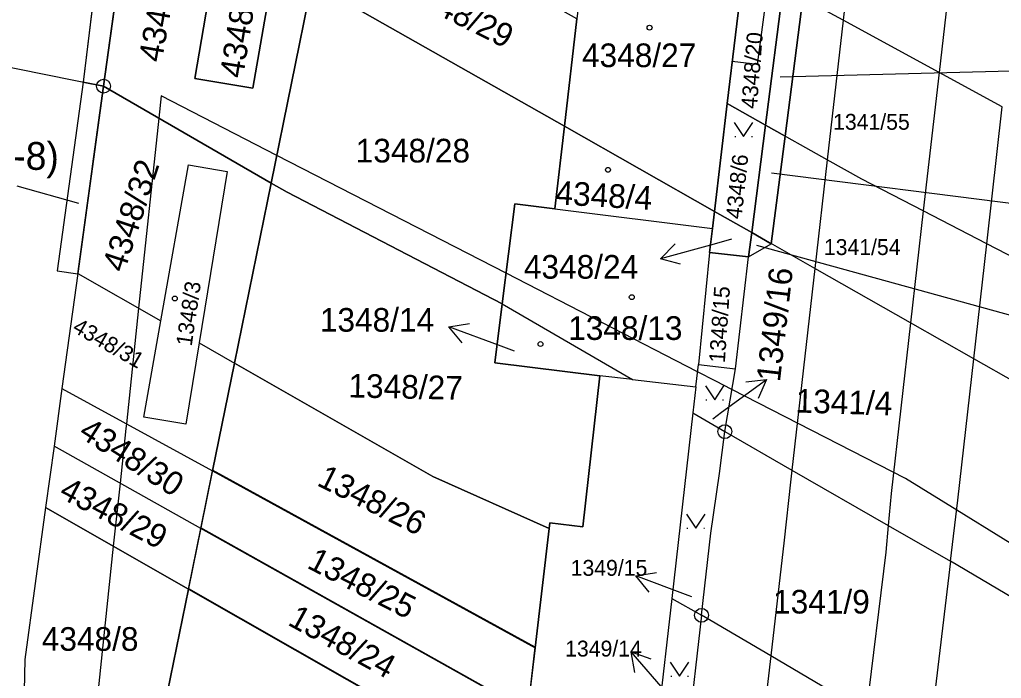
# Model space of a CAD drawing. Extents: x -735036 to -734743, y -1144813 to -1144181.
# Drawn here: x -734893.7 to -734823.1, y -1144606.3 to -1144559 of the extents above; entities that cross this region are included whole.
import ezdxf

# ---------------------------------------------------------------- set-up
doc = ezdxf.new("R2010")
doc.units = 0
for name, color, linetype in [('A3_SIT_OBJEKTY_N01', 7, 'Continuous'), ('BPEJ', 7, 'Continuous'), ('CKPLYN_POTRUBI_NT_PODZ_N', 7, 'Continuous'), ('Katastr_HRANICE DRÁHY', 7, 'Continuous'), ('Katastr_Hranice parcel', 7, 'Continuous'), ('Katastr_Parcelní čísla', 7, 'Continuous'), ('Katastr_pozemek SŽDC_šrafy', 7, 'Continuous'), ('Katastr_Slučkované čáry', 7, 'Continuous'), ('Katastr_Značky kultur', 7, 'Continuous'), ('ZÁBORY_dočasné', 7, 'Continuous'), ('ZÁBORY_dočasné_šrafy', 7, 'Continuous')]:
    doc.layers.add(name, color=color, linetype=linetype)

msp = doc.modelspace()

# ---------------------------------------------------------------- linework, layer by layer
at = {"layer": 'A3_SIT_OBJEKTY_N01'}
for points in [[(-734888.44, -1144569.554), (-734887.65, -1144563.8), (-734885.58, -1144548.75), (-734874.6, -1144550.79), (-734868.084, -1144506.936)], [(-734833.069, -1144512.138), (-734834.23, -1144521.36), (-734836.63, -1144539.96), (-734838.79, -1144556.7), (-734840.06, -1144566.59), (-734840.228, -1144567.714), (-734841.06, -1144574.32)]]:
    msp.add_lwpolyline(points, dxfattribs=at)
at = {"layer": 'BPEJ'}
msp.add_lwpolyline([(-734813, -1144602.5), (-734826.32, -1144594.27), (-734830, -1144592), (-734842.48, -1144585.59), (-734843.64, -1144584.99), (-734844.95, -1144584.32), (-734858.71, -1144577.24), (-734875.19, -1144568.77), (-734883.5, -1144564.5), (-734883.67, -1144566.1), (-734885.13, -1144579.76), (-734886.01, -1144588.05), (-734886.05, -1144588.39), (-734886.47, -1144592.33), (-734886.95, -1144596.85), (-734888.29, -1144609.47)], dxfattribs=at)
at = {"layer": 'CKPLYN_POTRUBI_NT_PODZ_N'}
msp.add_line((-734840.638, -1144562.238), (-734842.453, -1144562.022), dxfattribs=at)
msp.add_lwpolyline([(-734840.638, -1144562.238), (-734835.108, -1144520.855), (-734845.346, -1144519.67)], dxfattribs=at)
at = {"layer": 'Katastr_HRANICE DRÁHY'}
for points in [[(-734885.58, -1144548.75), (-734887.65, -1144563.8)], [(-734840.06, -1144566.59), (-734838.79, -1144556.7)], [(-734887.65, -1144563.8), (-734889.5, -1144577.27)], [(-734841.06, -1144574.32), (-734840.06, -1144566.59)], [(-734841.28, -1144576.06), (-734841.06, -1144574.32)], [(-734842.23, -1144584.11), (-734841.28, -1144576.06)], [(-734889.5, -1144577.27), (-734890.64, -1144585.51)], [(-734858.99, -1144579.44), (-734859.52, -1144583.67)], [(-734858.99, -1144579.44), (-734849.62, -1144584.88)], [(-734859.52, -1144583.67), (-734851.98, -1144584.62)], [(-734849.62, -1144584.88), (-734851.98, -1144584.62)], [(-734842.99, -1144588.62), (-734842.23, -1144584.11)], [(-734890.64, -1144585.51), (-734891.21, -1144589.67)], [(-734843.38, -1144591.64), (-734842.99, -1144588.62)], [(-734891.21, -1144589.67), (-734891.82, -1144594.07)], [(-734843.99, -1144595.92), (-734843.38, -1144591.64)], [(-734891.82, -1144594.07), (-734893.32, -1144605)], [(-734844.66, -1144601.82), (-734843.99, -1144595.92)], [(-734844.66, -1144601.82), (-734845.64, -1144610.44)], [(-734893.32, -1144605), (-734893.39, -1144608.37)]]:
    msp.add_lwpolyline(points, dxfattribs=at)
at = {"layer": 'Katastr_Hranice parcel'}
for points in [[(-734881.1, -1144563.24), (-734879.37, -1144553.15)], [(-734875.18, -1144553.88), (-734876.93, -1144563.95)], [(-734842.81, -1144565.04), (-734841.63, -1144555.15)], [(-734875.6, -1144570.76), (-734872.67, -1144556.37)], [(-734854.52, -1144566.67), (-734872.67, -1144556.37)], [(-734834.48, -1144559.05), (-734838.79, -1144556.7)], [(-734853.62, -1144558.97), (-734854.52, -1144566.67)], [(-734827.58, -1144562.82), (-734834.48, -1144559.05)], [(-734902.26, -1144560.85), (-734887.65, -1144563.8)], [(-734823.06, -1144565.29), (-734827.58, -1144562.82)], [(-734876.93, -1144563.95), (-734881.1, -1144563.24)], [(-734875.6, -1144570.76), (-734887.65, -1144563.8)], [(-734843.73, -1144572.8), (-734842.81, -1144565.04)], [(-734840.06, -1144566.59), (-734842.81, -1144565.04)], [(-734824.16, -1144575.12), (-734823.06, -1144565.29)], [(-734854.52, -1144566.67), (-734855.22, -1144572.62)], [(-734843.73, -1144572.8), (-734854.52, -1144566.67)], [(-734835.63, -1144569.08), (-734840.06, -1144566.59)], [(-734833.15, -1144570.47), (-734835.63, -1144569.08)], [(-734883.54, -1144580.67), (-734881.54, -1144569.44)], [(-734881.54, -1144569.44), (-734878.76, -1144569.92)], [(-734878.76, -1144569.92), (-734880.78, -1144582.24)], [(-734828.72, -1144572.76), (-734833.15, -1144570.47)], [(-734878.24, -1144583.69), (-734875.6, -1144570.76)], [(-734874.46, -1144571.42), (-734875.6, -1144570.76)], [(-734858.99, -1144579.44), (-734874.46, -1144571.42)], [(-734858.08, -1144572.26), (-734858.99, -1144579.44)], [(-734855.22, -1144572.62), (-734858.08, -1144572.26)], [(-734855.22, -1144572.62), (-734843.88, -1144574.02)], [(-734843.88, -1144574.02), (-734843.73, -1144572.8)], [(-734841.06, -1144574.32), (-734843.73, -1144572.8)], [(-734824.16, -1144575.12), (-734828.72, -1144572.76)], [(-734844.09, -1144575.76), (-734843.88, -1144574.02)], [(-734836.52, -1144576.89), (-734841.06, -1144574.32)], [(-734825.09, -1144583.38), (-734824.16, -1144575.12)], [(-734808.84, -1144583.03), (-734824.16, -1144575.12)], [(-734844.09, -1144575.76), (-734844.89, -1144583.8)], [(-734841.28, -1144576.06), (-734844.09, -1144575.76)], [(-734829.64, -1144580.8), (-734836.52, -1144576.89)], [(-734889.5, -1144577.27), (-734883.54, -1144580.67)], [(-734884.76, -1144587.57), (-734883.54, -1144580.67)], [(-734825.09, -1144583.38), (-734829.64, -1144580.8)], [(-734880.78, -1144582.24), (-734881.74, -1144588.08)], [(-734880.78, -1144582.24), (-734878.24, -1144583.69)], [(-734879.82, -1144591.44), (-734878.24, -1144583.69)], [(-734878.24, -1144583.69), (-734863.97, -1144591.84)], [(-734845.07, -1144585.39), (-734844.89, -1144583.8)], [(-734844.89, -1144583.8), (-734842.23, -1144584.11)], [(-734826.23, -1144593.55), (-734825.09, -1144583.38)], [(-734809.87, -1144592.02), (-734825.09, -1144583.38)], [(-734851.98, -1144584.62), (-734853.19, -1144595.45)], [(-734849.62, -1144584.88), (-734845.07, -1144585.39)], [(-734845.07, -1144585.39), (-734845.28, -1144587.28)], [(-734890.64, -1144585.51), (-734879.82, -1144591.44)], [(-734845.28, -1144587.28), (-734846.8, -1144600.6)], [(-734845.28, -1144587.28), (-734842.99, -1144588.62)], [(-734881.74, -1144588.08), (-734884.76, -1144587.57)], [(-734842.99, -1144588.62), (-734838.18, -1144591.38)], [(-734880.66, -1144595.58), (-734891.21, -1144589.67)], [(-734880.66, -1144595.58), (-734879.82, -1144591.44)], [(-734879.82, -1144591.44), (-734856.63, -1144604.15)], [(-734838.18, -1144591.38), (-734831.24, -1144595.37)], [(-734855.61, -1144595.57), (-734863.97, -1144591.84)], [(-734826.76, -1144597.94), (-734826.23, -1144593.55)], [(-734891.82, -1144594.07), (-734881.55, -1144599.93)], [(-734855.56, -1144595.17), (-734855.61, -1144595.57)], [(-734853.19, -1144595.45), (-734855.56, -1144595.17)], [(-734881.55, -1144599.93), (-734880.66, -1144595.58)], [(-734857.17, -1144608.74), (-734880.66, -1144595.58)], [(-734855.61, -1144595.57), (-734856.63, -1144604.15)], [(-734831.24, -1144595.37), (-734826.76, -1144597.94)], [(-734826.76, -1144597.94), (-734828.38, -1144611.37)], [(-734811.57, -1144606.92), (-734826.76, -1144597.94)], [(-734883.7, -1144610.47), (-734881.55, -1144599.93)], [(-734881.55, -1144599.93), (-734858.79, -1144612.91)], [(-734846.8, -1144600.6), (-734847.79, -1144609.19)], [(-734846.8, -1144600.6), (-734844.66, -1144601.82)], [(-734839.69, -1144604.74), (-734844.66, -1144601.82)], [(-734856.63, -1144604.15), (-734857.17, -1144608.74)], [(-734832.82, -1144608.77), (-734839.69, -1144604.74)]]:
    msp.add_lwpolyline(points, dxfattribs=at)
at = {"layer": 'Katastr_Parcelní čísla'}
for p, q in [((-734842.5, -1144574.79), (-734843.76, -1144575.14)), ((-734846.165, -1144576.578), (-734847.617, -1144576.2)), ((-734861.873, -1144582.25), (-734862.833, -1144581.096)), ((-734858.12, -1144582.83), (-734859.08, -1144582.48)), ((-734841.483, -1144585.031), (-734839.991, -1144584.869)), ((-734843.85, -1144587.69), (-734843.22, -1144587.23)), ((-734848.422, -1144600.148), (-734849.377, -1144598.991)), ((-734845.36, -1144600.49), (-734845.63, -1144600.39)), ((-734849.452, -1144605.917), (-734849.734, -1144604.442))]:
    msp.add_line(p, q, dxfattribs=at)
for points in [[(-734843.76, -1144575.14), (-734847.617, -1144576.2), (-734846.562, -1144575.132)], [(-734859.08, -1144582.48), (-734862.833, -1144581.096), (-734861.354, -1144580.842)], [(-734843.22, -1144587.23), (-734839.991, -1144584.869), (-734840.598, -1144586.242)], [(-734845.63, -1144600.39), (-734849.377, -1144598.991), (-734847.897, -1144598.743)], [(-734847.12, -1144607.47), (-734849.734, -1144604.442), (-734848.317, -1144604.936)]]:
    msp.add_lwpolyline(points, dxfattribs=at)
at = {"layer": 'Katastr_pozemek SŽDC_šrafy'}
for points in [[(-734841.63, -1144555.15), (-734840.25, -1144543.49), (-734841.43, -1144543.35), (-734851.65, -1144542.13), (-734852.48, -1144549.23), (-734853.62, -1144558.97), (-734854.52, -1144566.67), (-734843.73, -1144572.8), (-734842.81, -1144565.04), (-734841.63, -1144555.15)], [(-734879.37, -1144553.15), (-734875.18, -1144553.88), (-734885.58, -1144548.75), (-734887.65, -1144563.8), (-734875.6, -1144570.76), (-734872.67, -1144556.37), (-734875.18, -1144553.88), (-734876.93, -1144563.95), (-734881.1, -1144563.24), (-734879.37, -1144553.15)], [(-734867.65, -1144551.09), (-734868.04, -1144554.63), (-734872.67, -1144556.37), (-734854.52, -1144566.67), (-734853.62, -1144558.97), (-734867.65, -1144551.09)], [(-734879.37, -1144553.15), (-734881.1, -1144563.24), (-734876.93, -1144563.95), (-734875.18, -1144553.88), (-734879.37, -1144553.15)], [(-734838.79, -1144556.7), (-734841.63, -1144555.15), (-734842.81, -1144565.04), (-734840.06, -1144566.59), (-734838.79, -1144556.7)], [(-734872.67, -1144556.37), (-734875.6, -1144570.76), (-734874.46, -1144571.42), (-734858.99, -1144579.44), (-734858.08, -1144572.26), (-734855.22, -1144572.62), (-734854.52, -1144566.67), (-734872.67, -1144556.37)], [(-734881.54, -1144569.44), (-734878.76, -1144569.92), (-734880.78, -1144582.24), (-734878.24, -1144583.69), (-734875.6, -1144570.76), (-734887.65, -1144563.8), (-734889.5, -1144577.27), (-734883.54, -1144580.67), (-734881.54, -1144569.44)], [(-734840.06, -1144566.59), (-734842.81, -1144565.04), (-734843.73, -1144572.8), (-734841.06, -1144574.32), (-734840.06, -1144566.59)], [(-734858.99, -1144579.44), (-734874.46, -1144571.42), (-734875.6, -1144570.76), (-734878.24, -1144583.69), (-734863.97, -1144591.84), (-734855.61, -1144595.57), (-734855.56, -1144595.17), (-734853.19, -1144595.45), (-734851.98, -1144584.62), (-734859.52, -1144583.67), (-734858.99, -1144579.44)], [(-734841.06, -1144574.32), (-734843.73, -1144572.8), (-734843.88, -1144574.02), (-734844.09, -1144575.76), (-734841.28, -1144576.06), (-734841.06, -1144574.32)], [(-734863.97, -1144591.84), (-734878.24, -1144583.69), (-734879.82, -1144591.44), (-734856.63, -1144604.15), (-734855.61, -1144595.57), (-734863.97, -1144591.84)], [(-734879.811, -1144591.396), (-734880.651, -1144595.536), (-734857.161, -1144608.696), (-734856.621, -1144604.106), (-734879.811, -1144591.396)], [(-734881.55, -1144599.93), (-734891.82, -1144594.07), (-734893.32, -1144605), (-734893.39, -1144608.37), (-734884.47, -1144610.3), (-734883.7, -1144610.47), (-734881.55, -1144599.93)], [(-734880.651, -1144595.536), (-734881.541, -1144599.886), (-734858.781, -1144612.866), (-734857.671, -1144612.996), (-734857.161, -1144608.696), (-734880.651, -1144595.536)], [(-734881.55, -1144599.93), (-734883.7, -1144610.47), (-734884.47, -1144610.3), (-734885.13, -1144613.52), (-734862.9, -1144627.38), (-734861.22, -1144612.64), (-734858.79, -1144612.91), (-734881.55, -1144599.93)]]:
    msp.add_lwpolyline(points, dxfattribs=at)
at = {"layer": 'Katastr_Slučkované čáry'}
for points in [[(-734832.56, -1144542.21), (-734834.48, -1144559.05)], [(-734825.66, -1144546.02), (-734827.58, -1144562.82)], [(-734834.48, -1144559.05), (-734835.63, -1144569.08)], [(-734827.58, -1144562.82), (-734828.72, -1144572.76)], [(-734835.63, -1144569.08), (-734836.52, -1144576.89)], [(-734828.72, -1144572.76), (-734829.64, -1144580.8)], [(-734836.52, -1144576.89), (-734838.18, -1144591.38)], [(-734829.64, -1144580.8), (-734831.04, -1144593.06)], [(-734838.18, -1144591.38), (-734838.28, -1144592.26)], [(-734838.28, -1144592.26), (-734838.72, -1144596.41)], [(-734831.04, -1144593.06), (-734831.24, -1144595.37)], [(-734831.24, -1144595.37), (-734831.41, -1144597.28)], [(-734838.72, -1144596.41), (-734839.69, -1144604.74)], [(-734831.41, -1144597.28), (-734832.82, -1144608.77)], [(-734839.69, -1144604.74), (-734840.68, -1144613.32)]]:
    msp.add_lwpolyline(points, dxfattribs=at)
at = {"layer": 'Katastr_Značky kultur'}
for p, q in [((-734887.7, -1144563.8), (-734887.6, -1144563.8)), ((-734842.31, -1144566.415), (-734841.64, -1144567.42)), ((-734841.64, -1144567.42), (-734840.97, -1144566.415)), ((-734842.277, -1144567.42), (-734842.21, -1144567.42)), ((-734841.071, -1144567.42), (-734841.003, -1144567.42)), ((-734844.39, -1144585.325), (-734843.72, -1144586.33)), ((-734843.72, -1144586.33), (-734843.05, -1144585.325)), ((-734844.356, -1144586.33), (-734844.29, -1144586.33)), ((-734843.15, -1144586.33), (-734843.084, -1144586.33)), ((-734843.04, -1144588.62), (-734842.94, -1144588.62)), ((-734845.75, -1144594.545), (-734845.08, -1144595.55)), ((-734845.08, -1144595.55), (-734844.41, -1144594.545)), ((-734845.716, -1144595.55), (-734845.65, -1144595.55)), ((-734844.51, -1144595.55), (-734844.443, -1144595.55)), ((-734844.71, -1144601.82), (-734844.61, -1144601.82)), ((-734846.91, -1144605.185), (-734846.24, -1144606.19)), ((-734846.24, -1144606.19), (-734845.57, -1144605.185)), ((-734846.877, -1144606.19), (-734846.81, -1144606.19)), ((-734845.671, -1144606.19), (-734845.603, -1144606.19))]:
    msp.add_line(p, q, dxfattribs=at)
for centre, radius in [((-734848.4, -1144559.59), 0.175), ((-734887.65, -1144563.8), 0.499), ((-734851.39, -1144569.81), 0.175), ((-734882.53, -1144579.05), 0.175), ((-734849.68, -1144578.96), 0.175), ((-734856.24, -1144582.33), 0.175), ((-734842.99, -1144588.62), 0.499), ((-734844.66, -1144601.82), 0.499)]:
    msp.add_circle(centre, radius, dxfattribs=at)
at = {"layer": 'ZÁBORY_dočasné'}
for p, q in [((-734885.58, -1144548.75), (-734887.65, -1144563.8)), ((-734887.41, -1144549.49), (-734889.125, -1144563.502)), ((-734838.79, -1144556.7), (-734840.06, -1144566.59)), ((-734837.377, -1144557.471), (-734838.649, -1144567.383)), ((-734792.001, -1144561.929), (-734839, -1144563.153)), ((-734889.125, -1144563.502), (-734890.986, -1144577.066)), ((-734889.125, -1144563.502), (-734887.65, -1144563.8)), ((-734887.65, -1144563.8), (-734889.5, -1144577.27)), ((-734840.06, -1144566.59), (-734841.06, -1144574.32)), ((-734840.06, -1144566.59), (-734838.649, -1144567.383)), ((-734838.65, -1144567.383), (-734839.651, -1144575.118)), ((-734796.766, -1144575.479), (-734839.642, -1144570.052)), ((-734893.891, -1144570.961), (-734889.449, -1144572.201)), ((-734841.06, -1144574.32), (-734841.28, -1144576.059)), ((-734841.06, -1144574.32), (-734839.651, -1144575.118)), ((-734841.28, -1144576.06), (-734839.651, -1144575.118)), ((-734840.703, -1144575.228), (-734796.525, -1144587.399)), ((-734890.986, -1144577.066), (-734889.5, -1144577.271))]:
    msp.add_line(p, q, dxfattribs=at)
at = {"layer": 'ZÁBORY_dočasné_šrafy'}
for points in [[(-734885.58, -1144548.75), (-734887.18, -1144547.81), (-734887.41, -1144549.49), (-734889.125, -1144563.502), (-734887.65, -1144563.8), (-734885.58, -1144548.75)], [(-734837.377, -1144557.47), (-734838.79, -1144556.699), (-734840.06, -1144566.589), (-734838.649, -1144567.382), (-734837.377, -1144557.47)], [(-734887.65, -1144563.8), (-734889.125, -1144563.502), (-734890.986, -1144577.066), (-734889.5, -1144577.271), (-734887.65, -1144563.8)], [(-734838.65, -1144567.382), (-734840.06, -1144566.589), (-734841.06, -1144574.319), (-734839.651, -1144575.117), (-734838.65, -1144567.382)], [(-734841.06, -1144574.319), (-734841.28, -1144576.059), (-734839.651, -1144575.117), (-734841.06, -1144574.319)]]:
    msp.add_lwpolyline(points, dxfattribs=at)

# ---------------------------------------------------------------- texts
at = {"layer": 'Katastr_Parcelní čísla'}
for s, height, rotation, p in [('4348/33', 1.7, 80.02647, (-734883.471, -1144562.144)), ('4348/5', 1.7, 80.96139, (-734877.631, -1144563.281)), ('1348/29', 1.7, 333.39276, (-734866.103, -1144557.435)), ('4348/20', 1.14, 85.455, (-734840.688, -1144565.457)), ('4348/32', 1.7, 71.92764, (-734886.167, -1144577.248)), ('4348/6', 1.14, 83.8845, (-734841.793, -1144573.389)), ('4348/4', 1.7, 356.64444, (-734855.201, -1144572.285)), ('1349/16', 1.7, 83.39346, (-734839.03, -1144585.09)), ('1348/3', 1.14, 81.64926, (-734881.32, -1144582.524)), ('1348/15', 1.14, 86.06448, (-734842.99, -1144583.708)), ('4348/31', 1.14, 330.23547, (-734889.96, -1144581.39)), ('1348/27', 1.7, 358.76061, (-734870.063, -1144586.158)), ('1341/4', 1.7, 358.29018, (-734837.921, -1144587.244)), ('4348/30', 1.7, 327.42684, (-734889.533, -1144588.935)), ('1348/26', 1.7, 333.43497, (-734872.385, -1144592.448)), ('4348/29', 1.7, 332.34471, (-734890.941, -1144593.302)), ('1348/25', 1.7, 332.82063, (-734873.104, -1144598.377)), ('1348/24', 1.7, 331.31088, (-734874.487, -1144602.47))]:
    msp.add_text(s, height=height, rotation=rotation, dxfattribs=at).set_placement(p)
for s, height, p in [('4348/27', 1.7, (-734853.257, -1144562.43)), ('1341/55', 1.14, (-734835.206, -1144566.93)), ('1348/28', 1.7, (-734869.524, -1144569.28)), ('1341/54', 1.14, (-734835.869, -1144575.93)), ('4348/24', 1.7, (-734857.436, -1144577.63)), ('1348/14', 1.7, (-734872.104, -1144581.44)), ('1348/13', 1.7, (-734854.251, -1144582.03)), ('1349/15', 1.14, (-734854.071, -1144598.98)), ('1341/9', 1.7, (-734839.521, -1144601.69)), ('4348/8', 1.7, (-734892.093, -1144604.37)), ('1349/14', 1.14, (-734854.469, -1144604.78))]:
    msp.add_text(s, height=height, dxfattribs=at).set_placement(p)
at = {"layer": 'ZÁBORY_dočasné'}
msp.add_text('DOČASNÝ ZÁBOR POZEMKU (DZ-8)', height=2, rotation=359.37885, dxfattribs=at).set_placement((-734936.491, -1144569.334))

doc.saveas('drawing.dxf')
